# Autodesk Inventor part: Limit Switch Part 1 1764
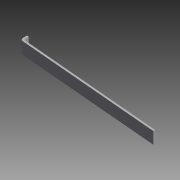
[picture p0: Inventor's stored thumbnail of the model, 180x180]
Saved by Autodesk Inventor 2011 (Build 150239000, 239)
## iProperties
Shininess: 0.0
Created: 2002-01
Part Number: Limit Switch Part 1 1764
Document SubType Name: Modeling
Density: 2.71 g/cm^3
Material: Aluminum-6061
Mass: 0.379544 g
Surface Area: 5.13202 cm^2
Volume: 0.140053 cm^3
Density: 0.0
Volumn: 0.0
Area: 0.0
PropertySet Name: Model Information
Control State: 0
Master: False
Checked Out: False
Author: Administrator
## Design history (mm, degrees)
node "Base1"
body "Solid1"
